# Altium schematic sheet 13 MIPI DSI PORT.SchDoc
size 420 x 297 mm
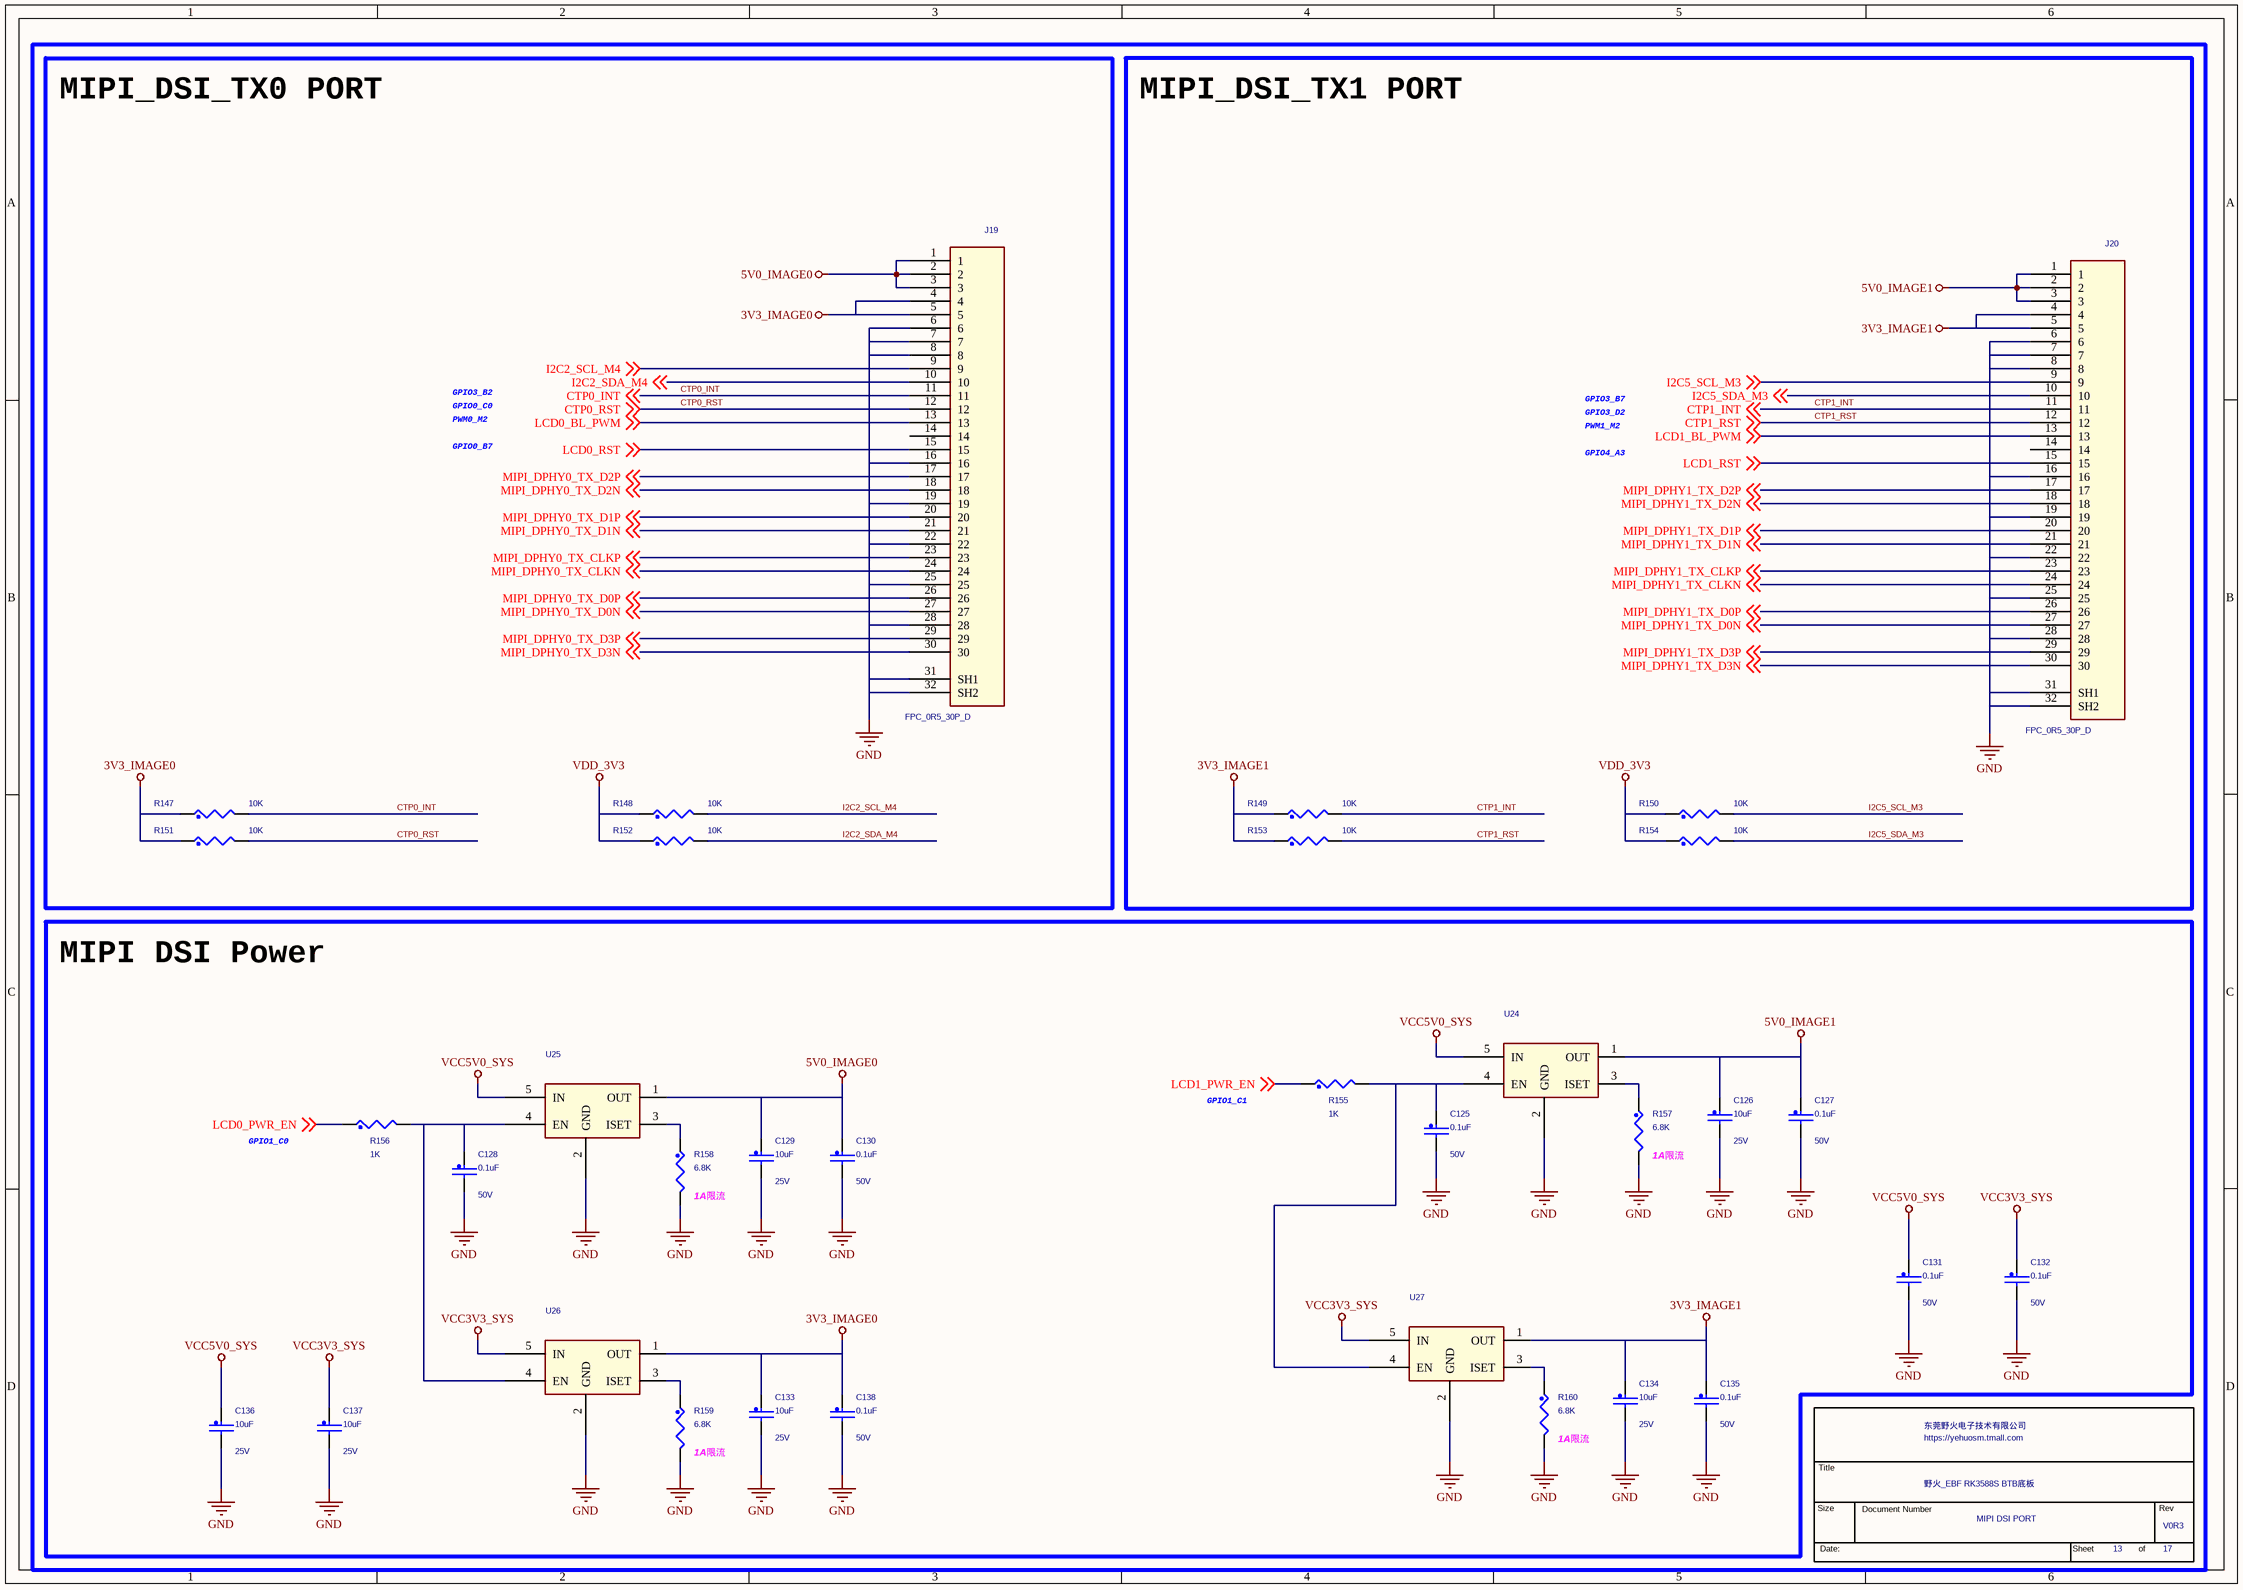
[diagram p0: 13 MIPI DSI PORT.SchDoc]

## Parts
*  Page Count: 17  Page Number: 13  OrgName: 东莞野火电子技术有限公司  Title: 野火_EBF RK3588S BTB底板  RevCode: V0R3  Doc: MIPI DSI PORT  (hidden comment: TitleBlock_YHSCH)  (graphical)
C125  0.1uF  Voltage: 50V  [C0402]
C126  10uF  Voltage: 25V  [C0603]
C127  0.1uF  Voltage: 50V  [C0402]
C128  0.1uF  Voltage: 50V  [C0402]
C129  10uF  Voltage: 25V  [C0603]
C130  0.1uF  Voltage: 50V  [C0402]
C131  0.1uF  Voltage: 50V  [C0402]
C132  0.1uF  Voltage: 50V  [C0402]
C133  10uF  Voltage: 25V  [C0603]
C134  10uF  Voltage: 25V  [C0603]
C135  0.1uF  Voltage: 50V  [C0402]
C136  10uF  Voltage: 25V  [C0603]
C137  10uF  Voltage: 25V  [C0603]
C138  0.1uF  Voltage: 50V  [C0402]
J19  FPC_0R5_30P_D  [FPC-30P-0P5]
J20  FPC_0R5_30P_D  [FPC-30P-0P5]
R147  10K  [R0402]
R148  10K  [R0402]
R149  10K  [R0402]
R150  10K  [R0402]
R151  10K  [R0402]
R152  10K  [R0402]
R153  10K  [R0402]
R154  10K  [R0402]
R155  1K  [R0402]
R156  1K  [R0402]
R157  6.8K  [R0402]
R158  6.8K  [R0402]
R159  6.8K  [R0402]
R160  6.8K  [R0402]
U24  (no value)  [SOT23-5]
U25  (no value)  [SOT23-5]
U26  (no value)  [SOT23-5]
U27  (no value)  [SOT23-5]

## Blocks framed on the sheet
MIPI_DSI_TX0 PORT: J19 R147 R148 R151 R152
MIPI_DSI_TX1 PORT: J20 R149 R150 R153 R154
MIPI DSI Power: C125-C138 R155-R160 U24-U27

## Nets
3V3_IMAGE0: C133.1 C138.1 J19.4 J19.5 R147.1 R151.1 U26.1(OUT)
3V3_IMAGE1: C134.1 C135.1 J20.4 J20.5 R149.1 R153.1 U27.1(OUT)
5V0_IMAGE0: C129.1 C130.1 J19.1 J19.2 J19.3 U25.1(OUT)
5V0_IMAGE1: C126.1 C127.1 J20.1 J20.2 J20.3 U24.1(OUT)
GND: C125.2 C126.2 C127.2 C128.2 C129.2 C130.2 C131.2 C132.2 C133.2 C134.2 C135.2 C136.2 C137.2 C138.2 J19.6 J19.7 J19.8 J19.16 J19.19 J19.22 J19.25 J19.28 J19.31(SH1) J19.32(SH2) J20.6 J20.7 J20.8 J20.16 J20.19 J20.22 J20.25 J20.28 J20.31(SH1) J20.32(SH2) R157.2 R158.2 R159.2 R160.2 U24.2(GND) U25.2(GND) U26.2(GND) U27.2(GND)
VCC3V3_SYS: C132.1 C137.1 U26.5(IN) U27.5(IN)
VCC5V0_SYS: C131.1 C136.1 U24.5(IN) U25.5(IN)
VDD_3V3: R148.1 R150.1 R152.1 R154.1
CTP0_INT: J19.11 R147.2 ; off-sheet CTP0_INT
CTP0_RST: J19.12 R151.2 ; off-sheet CTP0_RST
CTP1_INT: J20.11 R149.2 ; off-sheet CTP1_INT
CTP1_RST: J20.12 R153.2 ; off-sheet CTP1_RST
I2C2_SCL_M4: J19.9 R148.2 ; off-sheet I2C2_SCL_M4
I2C2_SDA_M4: J19.10 R152.2 ; off-sheet I2C2_SDA_M4
I2C5_SCL_M3: J20.9 R150.2 ; off-sheet I2C5_SCL_M3
I2C5_SDA_M3: J20.10 R154.2 ; off-sheet I2C5_SDA_M3
LCD0_BL_PWM: J19.13 ; off-sheet LCD0_BL_PWM
LCD0_PWR_EN: R156.1 ; off-sheet LCD0_PWR_EN
LCD0_RST: J19.15 ; off-sheet LCD0_RST
LCD1_BL_PWM: J20.13 ; off-sheet LCD1_BL_PWM
LCD1_PWR_EN: R155.1 ; off-sheet LCD1_PWR_EN
LCD1_RST: J20.15 ; off-sheet LCD1_RST
MIPI_DPHY0_TX_CLKN: J19.24 ; off-sheet MIPI_DPHY0_TX_CLKN
MIPI_DPHY0_TX_CLKP: J19.23 ; off-sheet MIPI_DPHY0_TX_CLKP
MIPI_DPHY0_TX_D0N: J19.27 ; off-sheet MIPI_DPHY0_TX_D0N
MIPI_DPHY0_TX_D0P: J19.26 ; off-sheet MIPI_DPHY0_TX_D0P
MIPI_DPHY0_TX_D1N: J19.21 ; off-sheet MIPI_DPHY0_TX_D1N
MIPI_DPHY0_TX_D1P: J19.20 ; off-sheet MIPI_DPHY0_TX_D1P
MIPI_DPHY0_TX_D2N: J19.18 ; off-sheet MIPI_DPHY0_TX_D2N
MIPI_DPHY0_TX_D2P: J19.17 ; off-sheet MIPI_DPHY0_TX_D2P
MIPI_DPHY0_TX_D3N: J19.30 ; off-sheet MIPI_DPHY0_TX_D3N
MIPI_DPHY0_TX_D3P: J19.29 ; off-sheet MIPI_DPHY0_TX_D3P
MIPI_DPHY1_TX_CLKN: J20.24 ; off-sheet MIPI_DPHY1_TX_CLKN
MIPI_DPHY1_TX_CLKP: J20.23 ; off-sheet MIPI_DPHY1_TX_CLKP
MIPI_DPHY1_TX_D0N: J20.27 ; off-sheet MIPI_DPHY1_TX_D0N
MIPI_DPHY1_TX_D0P: J20.26 ; off-sheet MIPI_DPHY1_TX_D0P
MIPI_DPHY1_TX_D1N: J20.21 ; off-sheet MIPI_DPHY1_TX_D1N
MIPI_DPHY1_TX_D1P: J20.20 ; off-sheet MIPI_DPHY1_TX_D1P
MIPI_DPHY1_TX_D2N: J20.18 ; off-sheet MIPI_DPHY1_TX_D2N
MIPI_DPHY1_TX_D2P: J20.17 ; off-sheet MIPI_DPHY1_TX_D2P
MIPI_DPHY1_TX_D3N: J20.30 ; off-sheet MIPI_DPHY1_TX_D3N
MIPI_DPHY1_TX_D3P: J20.29 ; off-sheet MIPI_DPHY1_TX_D3P
NetC125_1: C125.1 R155.2 U24.4(EN) U27.4(EN)
NetC128_1: C128.1 R156.2 U25.4(EN) U26.4(EN)
NetR157_1: R157.1 U24.3(ISET)
NetR158_1: R158.1 U25.3(ISET)
NetR159_1: R159.1 U26.3(ISET)
NetR160_1: R160.1 U27.3(ISET)

Not connected (* = marked no-connect by the designer): J19 14; J20 14

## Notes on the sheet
- GPIO3_B2
- GPIO0_C0
- PWM0_M2
- GPIO0_B7
- GPIO3_B7
- GPIO3_D2
- PWM1_M2
- GPIO4_A3
- GPIO1_C1
- GPIO1_C0
- (near R158) 1A限流
- (near R157) 1A限流
- (near R159) 1A限流
- (near R160) 1A限流

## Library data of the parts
* = TitleBlock_YHSCH: Cage Code: 1
C125 C128 C131 = CAP_NP: CLASS: DISCRETE; 生命周期: 量产; 价格: 0.029826; 规格书: 风华电容.pdf; 类别: 贴片电容0402; 品牌: 风华; 条码: EBF29060118; 规格编号: 0402X104K500NT; 规格: 贴片电容0.1uF 10% 50V X5R 0402
C126 C129 C133 C134 C136 C137 = CAP_NP: CLASS: DISCRETE; 规格: 贴片电容10uF 20% 25V X5R 0603; 规格编号: CL10A106MA8NRNC; 条码: EBF29060171; 品牌: 三星; 类别: 贴片电容0603; 规格书: 三星电容.pdf; 价格: 0.109811; 生命周期: 量产
C127 C130 C132 C135 C138 = CAP_NP: CLASS: DISCRETE; 规格: 贴片电容0.1uF 10% 50V X5R 0402; 规格编号: 0402X104K500NT; 条码: EBF29060118; 品牌: 风华; 类别: 贴片电容0402; 规格书: 风华电容.pdf; 价格: 0.029826; 生命周期: 量产
J19 J20 = FPC-30P: 规格: FPC连接器 针脚数30 间距0.5mm 高度2.0mm 下接 卧贴 翻盖式; 规格编号: FPC-05F-30PH20; 条码: EBF29040079; 品牌: 讯普; 类别: FPC连接器; 规格书: FPC-05F-NPH20.pdf; 生命周期: 量产
R147 = RES: CLASS: DISCRETE; 生命周期: 量产; 价格: 0.002773; 规格书: 厚声-无铅厚膜电阻.pdf; 类别: 贴片电阻0402; 品牌: 厚声; 条码: EBF29070046; 规格编号: 0402WGF1002TCE; 规格: 贴片电阻10K 1% 1/16W 0402
R148 R150 = RES: CLASS: DISCRETE; 生命周期: 量产; 价格: 0.002773; 规格书: 厚声-无铅厚膜电阻.pdf; 品牌: 厚声; 规格编号: 0402WGF1002TCE; 类别: 贴片电阻0402; 条码: EBF29070046; 规格: 贴片电阻10K 1% 1/16W 0402
R149 R151 R153 = RES: CLASS: DISCRETE; 规格: 贴片电阻10K 1% 1/16W 0402; 规格编号: 0402WGF1002TCE; 条码: EBF29070046; 品牌: 厚声; 类别: 贴片电阻0402; 规格书: 厚声-无铅厚膜电阻.pdf; 价格: 0.002773; 生命周期: 量产
R152 R154 = RES: CLASS: DISCRETE; 生命周期: 量产; 价格: 0.002773; 规格书: 厚声-无铅厚膜电阻.pdf; 品牌: 厚声; 规格编号: 0402WGF1002TCE; 规格: 贴片电阻10K 1% 1/16W 0402; 条码: EBF29070046; 类别: 贴片电阻0402
R155 R156 = RES: CLASS: DISCRETE; 规格: 贴片电阻1K 1% 1/16W 0402; 规格编号: RI0402L1001FT; 条码: EBF29070050; 品牌: 合科泰; 类别: 贴片电阻0402; 规格书: 合科泰-RI系列电阻.pdf; 生命周期: 量产
R157-R160 = RES: CLASS: DISCRETE; 规格: 贴片电阻6.8K 1% 1/16W 0402; 规格编号: RI0402L6801FT; 条码: EBF29070052; 品牌: 合科泰; 类别: 贴片电阻0402; 规格书: 合科泰-RI系列电阻.pdf; 生命周期: 量产
U24-U27 = LPW5209AB5F: 规格: 集成电源开关 导通电阻：80mΩ 最大可设置保护电流：2.1A 输入电压：2.5V~6V 静态电流：30uA 其他功能：软启动、短路保护、热保护; 条码: EBF29280015; 品牌: 微源半导体; 类别: 功率开关; 规格书: 微源半导体_LPW5209AB5F.pdf; 价格: 0.468063; 生命周期: 量产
